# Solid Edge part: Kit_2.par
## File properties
Author: ahadarics
Last saved by: ahadarics
Revision: 76
Sűrűség: 0,000 kg/m^3
Pontosság: 0,990
Username: ahadarics
Dokumentum tartalom típus: 0
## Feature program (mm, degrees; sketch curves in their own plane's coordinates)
base feature "unnamed BaseFeature 1"
sketch for "Furat_1" plane through (0, 3.75, 13.5) normal (0, 0, 1) x-axis (0, 1, 0)
  hole centre (-0.25, 0) bore radius 4.283
hole "Furat_1" nominal diameter 9.728 finite  ThreadDepth = 7.5 mm
sketch for "unnamed Protrusion 1" #1 plane through (0, 33.5, 0) normal (0, 1, 0) x-axis (0, 0, -1)
  line (-7.5498, 8) -> (7.5498, 8)
sketch for "unnamed Protrusion 1" #2 plane through (0, 33.5, 0) normal (0, 1, 0) x-axis (0, 0, -1)
  line (-7.5498, -8) -> (7.5498, -8)
  arc centre (0, 0) radius 11 from (7.5498, -8) to (-7.5498, -8) cw
extrude "unnamed Protrusion 1" add to key point along -normal
thread "unnamed Thread 1"
chamfer "Letörés_1" setback 1.5
sketch for "Kivágás_1" #1 plane through (0, 33.5, 0) normal (0, 1, 0) x-axis (0, 0, -1)
  line (-7.5498, 8) -> (7.5498, 8)
sketch for "Kivágás_1" #2 plane through (0, 33.5, 0) normal (0, 1, 0) x-axis (0, 0, -1)
  line (-7.5498, -8) -> (7.5498, -8)
  arc centre (0, 0) radius 11 from (7.5498, -8) to (-7.5498, -8) cw
extrude "Kivágás_1" cut finite 20 along -normal
chamfer "Letörés_2" setback 0.7
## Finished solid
Body 1: solid body, 32 faces, 72 edges, 41 vertices.
  Faces by surface: plane 13, cylinder 11, cone 8
  Edges by curve: line 33, circle 31, intersection 4, spline 4
Bounding box of the edges (mm): 30.000 x 39.500 x 28.500, from (-15, -6, -15) to (15, 33.5, 13.5).
Cylindrical faces by radius (mm): R4 x1, R4.28 x1, R4.283 x1, R9.85 x2, R11 x4, R13.5 x1, R15 x1
Conical faces (half-angle, radius in mm at the cone's reference point): 45 deg R4.1 x2, 45 deg R4.983 x1, 45 deg R11 x2, 59 deg R2.1415 x1, 60 deg R10.425 x2
Planar faces by outward normal: +x 1, +y 7, +z 2, -x 1, -y 2
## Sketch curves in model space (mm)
arc centre (0, 33.5, 0) radius 11 from (8, 33.5, -7.5498) through (11, 33.5, 0) to (8, 33.5, 7.5498)
line (8, 33.5, 7.5498) -> (8, 33.5, -7.5498)
arc centre (0, 33.5, 0) radius 11 from (-8, 33.5, 7.5498) through (-11, 33.5, 0) to (-8, 33.5, -7.5498)
line (-8, 33.5, 7.5498) -> (-8, 33.5, -7.5498)
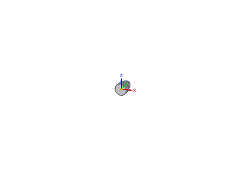
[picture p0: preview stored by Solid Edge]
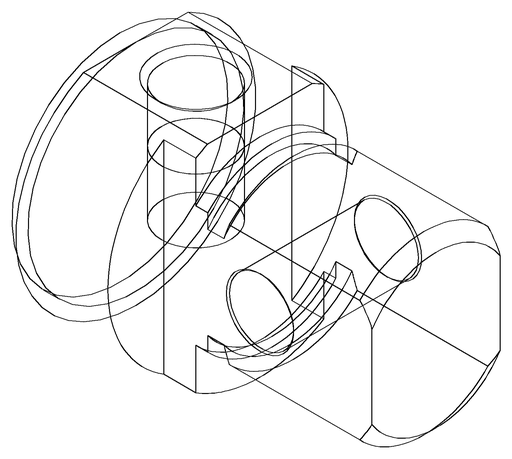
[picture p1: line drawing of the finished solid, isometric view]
